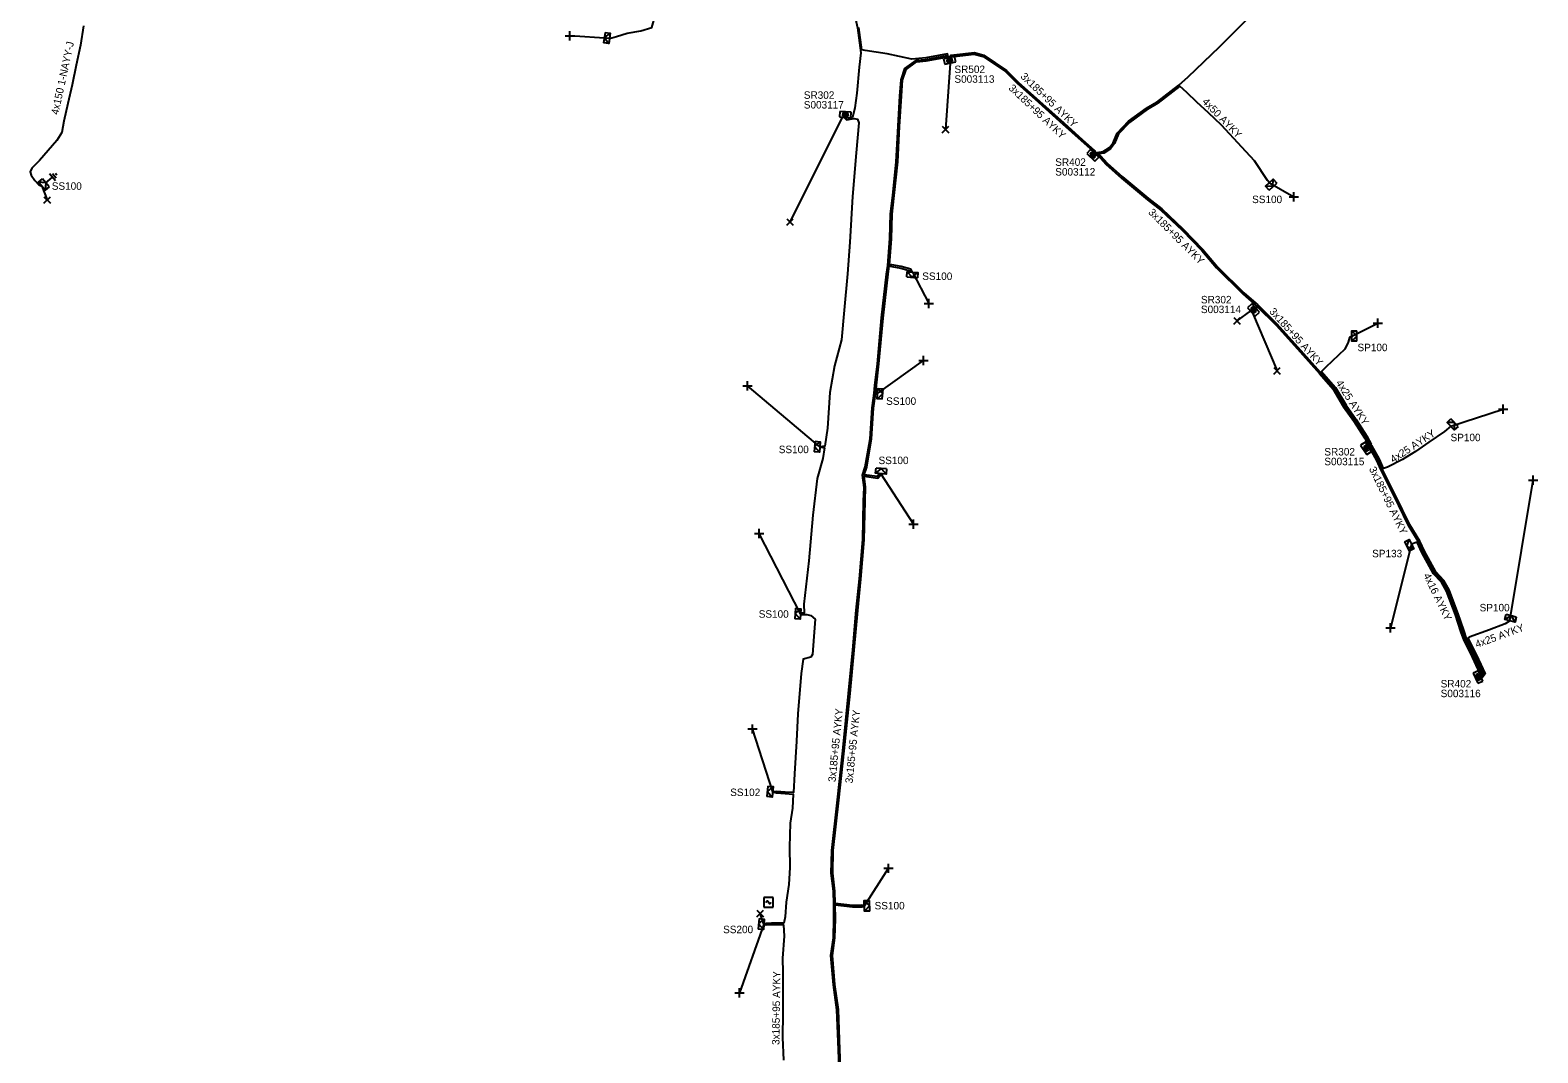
# Model space of a CAD drawing. Extents: x -763093 to -760976, y -1155572 to -1152009.
# Drawn here: x -762866.2 to -762664.6, y -1152405.9 to -1152269.2 of the extents above; entities that cross this region are included whole.
import ezdxf

# ---------------------------------------------------------------- set-up
doc = ezdxf.new("R2010")
doc.units = 0
for name, color, linetype in [('Vrstva 1', 7, 'Continuous'), ('Vrstva 14', 7, 'Continuous'), ('Vrstva 15', 7, 'Continuous'), ('Vrstva 28', 7, 'Continuous'), ('Vrstva 29', 7, 'Continuous'), ('Vrstva 30', 7, 'Continuous'), ('Vrstva 31', 7, 'Continuous'), ('Vrstva 33', 7, 'Continuous'), ('Vrstva 34', 7, 'Continuous'), ('Vrstva 5', 7, 'Continuous'), ('Vrstva 59', 7, 'Continuous'), ('Vrstva 6', 7, 'Continuous'), ('Vrstva 8', 7, 'Continuous'), ('Vrstva 9', 7, 'Continuous')]:
    doc.layers.add(name, color=color, linetype=linetype)

# ---------------------------------------------------------------- blocks, each defined once
blk = doc.blocks.new('NN800')
at = {"layer": 'Vrstva 1'}
for points in [[(-0.44, 0.44), (0.44, -0.44)], [(-0.44, -0.44), (0.44, 0.44)]]:
    blk.add_lwpolyline(points, dxfattribs=at)
blk = doc.blocks.new('NN620')
at = {"layer": 'Vrstva 8'}
for points in [[(0.75, 0), (-0.75, 0)], [(-0.75, 0), (-0.75, -0.75)], [(0.75, -0.75), (0.75, 0)], [(-0.75, -0.75), (0.75, -0.75)], [(0.37, -0.18), (-0.38, -0.18)], [(-0.38, -0.18), (-0.38, -0.56)], [(-0.38, -0.56), (0.37, -0.56)], [(0.32, -0.23), (-0.33, -0.23)], [(-0.33, -0.23), (-0.33, -0.51)], [(-0.33, -0.51), (0.32, -0.51)], [(0.27, -0.27), (-0.28, -0.27)], [(-0.28, -0.27), (-0.28, -0.46)], [(-0.28, -0.46), (0.27, -0.46)], [(0.23, -0.32), (-0.23, -0.32)], [(-0.23, -0.32), (-0.23, -0.42)], [(-0.23, -0.42), (0.23, -0.42)], [(-0.19, -0.37), (0.19, -0.37)], [(0.23, -0.42), (0.23, -0.32)], [(0.27, -0.46), (0.27, -0.27)], [(0.32, -0.51), (0.32, -0.23)], [(0.37, -0.56), (0.37, -0.18)]]:
    blk.add_lwpolyline(points, dxfattribs=at)
blk = doc.blocks.new('NN630')
at = {"layer": 'Vrstva 9'}
for points in [[(0, -0.7), (-0.7, 0)], [(-0.7, -0.7), (-0.7, 0), (0.7, 0), (0.7, -0.7)], [(-0.7, -0.7), (0.7, -0.7)], [(0, -0.7), (0.7, 0)]]:
    blk.add_lwpolyline(points, dxfattribs=at)
blk = doc.blocks.new('NN810')
at = {"layer": 'Vrstva 14'}
for points in [[(0.63, -1.89), (-0.62, -1.89)], [(0, -0.64), (0, -1.89)], [(0.39, -2.2), (-0.4, -2.2)], [(0, -2.52), (-0.12, -2.52)], [(0.14, -2.52), (0, -2.52)]]:
    blk.add_lwpolyline(points, dxfattribs=at)
blk = doc.blocks.new('NN740')
at = {"layer": 'Vrstva 1'}
for points in [[(0.62, 0.62), (-0.63, 0.62)], [(-0.63, 0.62), (-0.63, -0.63)], [(0, 0), (0, 0.01), (0, 0.03), (-0.01, 0.05), (-0.01, 0.06), (-0.02, 0.08), (-0.03, 0.09), (-0.04, 0.1), (-0.05, 0.11), (-0.06, 0.12), (-0.08, 0.13), (-0.09, 0.14), (-0.11, 0.14), (-0.12, 0.15), (-0.14, 0.15), (-0.15, 0.15), (-0.17, 0.15), (-0.18, 0.15), (-0.2, 0.15), (-0.21, 0.14), (-0.23, 0.13), (-0.24, 0.12), (-0.26, 0.11), (-0.27, 0.1), (-0.28, 0.09), (-0.29, 0.08), (-0.29, 0.06), (-0.3, 0.05), (-0.3, 0.03), (-0.31, 0.02), (-0.31, 0), (-0.31, 0)], [(0.62, -0.63), (0.62, 0.62)], [(-0.63, -0.63), (0.62, -0.63)], [(0, 0), (0, -0.02), (0, -0.03), (0.01, -0.05), (0.01, -0.06), (0.02, -0.08), (0.03, -0.09), (0.04, -0.1), (0.05, -0.11), (0.06, -0.12), (0.07, -0.13), (0.09, -0.14), (0.1, -0.15), (0.12, -0.15), (0.13, -0.15), (0.15, -0.15), (0.16, -0.15), (0.18, -0.15), (0.19, -0.15), (0.21, -0.14), (0.22, -0.14), (0.24, -0.13), (0.25, -0.12), (0.26, -0.11), (0.27, -0.09), (0.28, -0.08), (0.29, -0.07), (0.29, -0.05), (0.3, -0.04), (0.3, -0.02), (0.3, -0.01), (0.3, -0.01)]]:
    blk.add_lwpolyline(points, dxfattribs=at)

msp = doc.modelspace()

# ---------------------------------------------------------------- linework, layer by layer
at = {"layer": 'Vrstva 5'}
for points in [[(-762777.22, -1152244.01), (-762776.91, -1152243.04), (-762776.6, -1152242.48), (-762775.28, -1152243.88), (-762772.47, -1152245.98), (-762769.84, -1152248.34), (-762766.96, -1152250.61), (-762764.08, -1152252.76), (-762761.25, -1152255.63), (-762760.02, -1152256.98), (-762758.84, -1152259.01), (-762758.01, -1152260.5), (-762757.4, -1152261.86), (-762757.19, -1152263.08), (-762756.18, -1152265.93), (-762755.53, -1152268.93), (-762755.1, -1152272.27), (-762755.29, -1152274.2), (-762755.64, -1152277.65), (-762755.88, -1152279.62), (-762756.2, -1152280.89), (-762756.92, -1152280.98), (-762757.08, -1152280.85)], [(-762788.68, -1152270.34), (-762787.75, -1152270.1), (-762786.31, -1152269.64), (-762784.5, -1152269.34), (-762783.04, -1152268.9), (-762782.58, -1152267.32), (-762781.96, -1152263.9), (-762781.27, -1152262.03), (-762780.25, -1152259.57), (-762779.44, -1152256.84), (-762778.72, -1152252.78), (-762778.22, -1152249.01), (-762777.67, -1152246.04), (-762777.5, -1152245.02), (-762777.34, -1152245.06)], [(-762859.02, -1152268.65), (-762859.42, -1152271.23), (-762860, -1152273.9), (-762860.55, -1152276.53), (-762861.12, -1152279.05), (-762861.66, -1152281.42), (-762861.91, -1152282.92), (-762862.6, -1152283.97), (-762863.76, -1152285.3), (-762864.91, -1152286.67), (-762865.93, -1152287.69), (-762866.15, -1152288.16), (-762866, -1152288.62), (-762865.54, -1152289.35), (-762865.01, -1152289.93), (-762864.59, -1152290.1)], [(-762743.38, -1152272.93), (-762743.49, -1152272.42), (-762746.41, -1152272.94), (-762748.27, -1152273.12), (-762751.55, -1152272.38), (-762754.51, -1152271.97), (-762754.96, -1152271.85), (-762755.33, -1152268.89)], [(-762723.83, -1152285.69), (-762723.51, -1152285.6), (-762722.67, -1152285.47), (-762721.85, -1152284.92), (-762721.33, -1152284.3), (-762720.82, -1152283.01), (-762719.3, -1152281.41), (-762716.9, -1152279.66), (-762715.49, -1152278.85), (-762712.58, -1152276.58), (-762711.33, -1152275.47), (-762707.12, -1152271.46), (-762703.51, -1152267.85)], [(-762757.8, -1152413.28), (-762758.08, -1152405.45), (-762758.29, -1152400.15), (-762758.76, -1152396.81), (-762759.08, -1152392.88), (-762758.76, -1152390.54), (-762758.68, -1152387.98), (-762758.7, -1152386.03), (-762758.76, -1152384.31), (-762759.03, -1152381.88), (-762758.98, -1152378.85), (-762758.21, -1152372.1), (-762757.5, -1152365.54), (-762756.72, -1152357.88), (-762756.16, -1152352.07), (-762755.69, -1152346.77), (-762755.27, -1152342.58), (-762754.83, -1152337.31), (-762754.71, -1152332.19), (-762754.64, -1152330.34), (-762754.88, -1152328.72), (-762754.49, -1152327.58), (-762753.85, -1152323.84), (-762753.59, -1152319.72), (-762753.3, -1152317.75), (-762753.2, -1152316.68), (-762752.86, -1152313.81), (-762752.32, -1152307.69), (-762751.64, -1152301.83), (-762751.48, -1152300.67), (-762751.19, -1152297.09), (-762751.1, -1152293.79), (-762750.82, -1152291.3), (-762750.34, -1152286.82), (-762750.11, -1152282.08), (-762749.85, -1152278.02), (-762749.7, -1152275.89), (-762749.21, -1152274.36), (-762747.64, -1152273.26), (-762746.38, -1152273.14), (-762743.56, -1152272.64), (-762743.49, -1152272.95)], [(-762757.6, -1152413.28), (-762757.88, -1152405.45), (-762758.09, -1152400.13), (-762758.56, -1152396.79), (-762758.88, -1152392.88), (-762758.56, -1152390.56), (-762758.48, -1152387.98), (-762758.5, -1152386.14), (-762756.2, -1152386.4), (-762754.95, -1152386.38), (-762754.61, -1152386.27), (-762754.95, -1152386.18), (-762756.2, -1152386.2), (-762758.5, -1152385.94), (-762758.56, -1152384.29), (-762758.83, -1152381.88), (-762758.78, -1152378.87), (-762758.01, -1152372.12), (-762757.3, -1152365.56), (-762756.52, -1152357.9), (-762755.96, -1152352.09), (-762755.49, -1152346.79), (-762755.07, -1152342.6), (-762754.63, -1152337.33), (-762754.51, -1152332.19), (-762754.44, -1152330.32), (-762754.66, -1152328.85), (-762752.81, -1152329.1), (-762752.5, -1152328.76), (-762752.41, -1152328.51), (-762752.66, -1152328.63), (-762752.89, -1152328.88), (-762754.65, -1152328.65), (-762754.29, -1152327.62), (-762753.65, -1152323.86), (-762753.39, -1152319.74), (-762753.12, -1152317.87), (-762752.86, -1152317.81), (-762753.09, -1152317.67), (-762753, -1152316.7), (-762752.66, -1152313.83), (-762752.12, -1152307.71), (-762751.44, -1152301.85), (-762751.29, -1152300.79), (-762750.94, -1152300.82), (-762749.74, -1152301.04), (-762748.51, -1152301.38), (-762748.18, -1152301.57), (-762748.41, -1152301.2), (-762749.7, -1152300.84), (-762750.92, -1152300.62), (-762751.27, -1152300.59), (-762750.99, -1152297.11), (-762750.9, -1152293.81), (-762750.62, -1152291.32), (-762750.14, -1152286.84), (-762749.91, -1152282.1), (-762749.65, -1152278.04), (-762749.5, -1152275.93), (-762749.03, -1152274.48), (-762747.62, -1152273.46), (-762746.35, -1152273.34), (-762743.63, -1152272.86), (-762743.59, -1152273.03)], [(-762743.29, -1152272.91), (-762743.04, -1152272.59), (-762739.9, -1152272.23), (-762738.63, -1152272.56), (-762735.6, -1152274.61), (-762734.06, -1152276.17), (-762731.19, -1152278.74), (-762728.39, -1152281.24), (-762725.48, -1152283.83), (-762723.84, -1152285.3), (-762723.76, -1152285.59), (-762723.45, -1152285.6), (-762722.17, -1152287), (-762720.08, -1152288.84), (-762716.62, -1152291.75), (-762714.83, -1152293.13), (-762711.98, -1152295.84), (-762709.37, -1152298.56), (-762707.39, -1152300.86), (-762703.89, -1152304.34), (-762702.01, -1152305.95), (-762702.38, -1152306.31)], [(-762743.15, -1152272.88), (-762742.96, -1152272.79), (-762739.92, -1152272.43), (-762738.71, -1152272.74), (-762735.72, -1152274.77), (-762734.2, -1152276.31), (-762731.33, -1152278.88), (-762728.53, -1152281.38), (-762725.62, -1152283.97), (-762724.02, -1152285.42), (-762723.97, -1152285.56)], [(-762700.46, -1152289.63), (-762700.72, -1152289.33), (-762702.43, -1152286.72), (-762704.14, -1152284.86), (-762706.84, -1152281.95), (-762708.61, -1152280.27), (-762710.14, -1152278.88), (-762711.49, -1152277.58), (-762712.44, -1152276.73), (-762715.37, -1152279.01), (-762716.8, -1152279.82), (-762719.16, -1152281.57), (-762720.64, -1152283.11), (-762721.15, -1152284.4), (-762721.71, -1152285.08), (-762722.59, -1152285.67), (-762723.5, -1152285.8), (-762723.72, -1152285.79)], [(-762757.34, -1152280.88), (-762756.98, -1152281.2), (-762755.96, -1152281.05), (-762755.55, -1152281.15), (-762755.36, -1152281.6), (-762755.73, -1152285.65), (-762756.22, -1152291.48), (-762756.57, -1152297.56), (-762756.87, -1152301.81), (-762757.33, -1152306.65), (-762757.67, -1152310.61), (-762758.61, -1152314.09), (-762759.25, -1152317.67), (-762759.55, -1152322.43), (-762759.9, -1152324.85), (-762760.56, -1152324.93), (-762759.93, -1152325.05), (-762760.15, -1152326.47), (-762760.92, -1152329.17), (-762761.5, -1152334.06), (-762762.03, -1152340.14), (-762762.72, -1152345.93), (-762762.68, -1152347.14), (-762762.94, -1152347.15), (-762763.16, -1152347.25), (-762762.94, -1152347.35), (-762762.31, -1152347.33), (-762761.75, -1152347.47), (-762761.17, -1152347.97), (-762761.36, -1152350.28), (-762761.54, -1152352.66), (-762761.79, -1152353.03), (-762762.81, -1152353.28), (-762763.07, -1152355.21), (-762763.5, -1152360.61), (-762763.7, -1152364.24), (-762763.94, -1152368.62), (-762764.1, -1152371.12), (-762765.18, -1152371.05), (-762766.38, -1152370.97), (-762766.87, -1152371.03), (-762766.38, -1152371.17), (-762765.2, -1152371.25), (-762764.12, -1152371.32), (-762764.22, -1152373.21), (-762764.53, -1152375.22), (-762764.6, -1152378.43), (-762764.59, -1152381.16), (-762764.71, -1152383.43), (-762765.08, -1152385.77), (-762765.22, -1152387.72), (-762765.4, -1152388.58), (-762767.05, -1152388.56), (-762767.72, -1152388.61), (-762768.05, -1152388.73), (-762767.72, -1152388.81), (-762767.05, -1152388.76), (-762765.41, -1152388.78), (-762765.32, -1152390.32), (-762765.57, -1152393.24), (-762765.52, -1152395.18), (-762765.52, -1152400.62), (-762765.56, -1152403.85), (-762765.41, -1152406.87)], [(-762723.6, -1152285.9), (-762723.45, -1152285.9), (-762722.31, -1152287.14), (-762720.22, -1152289), (-762716.74, -1152291.91), (-762714.97, -1152293.29), (-762712.12, -1152295.98), (-762709.51, -1152298.7), (-762707.53, -1152301), (-762704.03, -1152304.48), (-762702.08, -1152306.16), (-762699.54, -1152308.68), (-762696.34, -1152312.24), (-762693.77, -1152315.11), (-762691.94, -1152317.23), (-762690.53, -1152319.57), (-762689.19, -1152321.48), (-762687.75, -1152323.7), (-762687.29, -1152324.6), (-762687.42, -1152324.69)], [(-762672.16, -1152355.64), (-762671.84, -1152355.22), (-762672.96, -1152352.86), (-762674.06, -1152350.65), (-762674.48, -1152349.44), (-762675.2, -1152347.23), (-762676.43, -1152344.05), (-762677.14, -1152342.77), (-762678.2, -1152341.64), (-762679.73, -1152338.87), (-762680.35, -1152337.52), (-762681.66, -1152335.33), (-762683.62, -1152331.32), (-762685.38, -1152327.85), (-762685.92, -1152326.65), (-762686.98, -1152324.76), (-762687.58, -1152323.6), (-762689.02, -1152321.37), (-762690.36, -1152319.46), (-762691.78, -1152317.11), (-762693.62, -1152314.98), (-762696.2, -1152312.1), (-762699.4, -1152308.54), (-762701.87, -1152306.09), (-762702.24, -1152306.45)], [(-762689.45, -1152310.11), (-762689.73, -1152310.32), (-762689.94, -1152310.95), (-762690.38, -1152311.87), (-762692.91, -1152314.27), (-762693.48, -1152314.84), (-762691.62, -1152316.99), (-762690.19, -1152319.35), (-762688.85, -1152321.26), (-762687.41, -1152323.5), (-762686.86, -1152324.56), (-762687.28, -1152324.84)], [(-762676.22, -1152322.16), (-762677.06, -1152322.86), (-762679.13, -1152324.29), (-762680.94, -1152325.56), (-762682.66, -1152326.6), (-762684.66, -1152327.66), (-762685.18, -1152327.8), (-762685.74, -1152326.56), (-762686.76, -1152324.74), (-762687.16, -1152325)], [(-762672.26, -1152355.44), (-762672.08, -1152355.2), (-762673.14, -1152352.94), (-762674.24, -1152350.73), (-762674.67, -1152349.51), (-762675.39, -1152347.3), (-762676.61, -1152344.13), (-762677.3, -1152342.89), (-762678.36, -1152341.76), (-762679.91, -1152338.96), (-762680.53, -1152337.6), (-762681.84, -1152335.43), (-762683.8, -1152331.4), (-762685.56, -1152327.93), (-762686.1, -1152326.74), (-762687, -1152325.13)], [(-762672.31, -1152355.17), (-762673.32, -1152353.03), (-762674.42, -1152350.82), (-762674.86, -1152349.58), (-762675.58, -1152347.37), (-762676.79, -1152344.21), (-762677.46, -1152343.01), (-762678.52, -1152341.88), (-762680.09, -1152339.05), (-762680.72, -1152337.67), (-762681.45, -1152337.94)], [(-762668.29, -1152348.18), (-762668.92, -1152348.58), (-762671.01, -1152349.37), (-762673.75, -1152350.37), (-762673.91, -1152350.5), (-762672.78, -1152352.77), (-762671.61, -1152355.25), (-762672.07, -1152355.85)]]:
    msp.add_lwpolyline(points, dxfattribs=at)
at = {"layer": 'Vrstva 59'}
for points in [[(-762788.68, -1152270.34), (-762794, -1152270)], [(-762743.15, -1152273.63), (-762743.75, -1152282.5)], [(-762757.57, -1152280.88), (-762764.56, -1152294.88)], [(-762700.46, -1152289.63), (-762697.19, -1152291.5)], [(-762864.59, -1152290.1), (-762863.89, -1152291.93)], [(-762748.18, -1152301.57), (-762746, -1152305.75)], [(-762702.98, -1152306.76), (-762704.79, -1152308.08)], [(-762702.73, -1152307.03), (-762699.44, -1152314.75)], [(-762689.45, -1152310.11), (-762685.94, -1152308.38)], [(-762752.86, -1152317.81), (-762746.69, -1152313.38)], [(-762760.56, -1152324.93), (-762770.25, -1152316.75)], [(-762676.22, -1152322.16), (-762669.19, -1152319.88)], [(-762752.41, -1152328.51), (-762748.06, -1152335.25)], [(-762668.29, -1152348.18), (-762665.19, -1152329.38)], [(-762763.16, -1152347.25), (-762768.69, -1152336.5)], [(-762681.45, -1152337.94), (-762684.25, -1152349.13)], [(-762766.87, -1152371.03), (-762769.56, -1152362.63)], [(-762754.61, -1152386.27), (-762751.38, -1152381.25)], [(-762768.05, -1152388.73), (-762768.56, -1152387.3)], [(-762768.05, -1152388.73), (-762771.31, -1152397.88)]]:
    msp.add_lwpolyline(points, dxfattribs=at)

# ---------------------------------------------------------------- block references
at = {"layer": 'Vrstva 15', "rotation": 130.60141040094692}
msp.add_blockref('NN810', (-762864.59, -1152290.1), dxfattribs=at)
at = {"layer": 'Vrstva 28'}
for p, rotation in [((-762743.29, -1152272.91), 11.863461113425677), ((-762757.18, -1152280.89), 176.12682012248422), ((-762723.83, -1152285.69), -42.35830100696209), ((-762702.31, -1152306.38), -47.00935499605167), ((-762687.22, -1152324.92), -57.46023708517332), ((-762672.21, -1152355.54), -66.73196604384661)]:
    msp.add_blockref('NN620', p, dxfattribs=dict(at, rotation=rotation))
at = {"layer": 'Vrstva 31'}
for p, rotation in [((-762788.68, -1152270.34), -98.00232040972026), ((-762864.59, -1152290.1), 130.60141040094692), ((-762700.46, -1152289.63), 42.45662503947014), ((-762748.18, -1152301.57), -3.9728303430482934), ((-762689.45, -1152310.11), 90), ((-762752.86, -1152317.81), 85.87478051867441), ((-762676.22, -1152322.16), 133.1402192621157), ((-762760.56, -1152324.93), -94.76171392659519), ((-762752.41, -1152328.51), 175.67250838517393), ((-762681.45, -1152337.94), -64.63601383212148), ((-762763.16, -1152347.25), -94.42481608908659), ((-762668.29, -1152348.18), 166.4073739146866), ((-762766.87, -1152371.03), -95.57836302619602), ((-762754.61, -1152386.27), 91.21513338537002), ((-762768.05, -1152388.73), -95.00694085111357)]:
    msp.add_blockref('NN630', p, dxfattribs=dict(at, rotation=rotation))
at = {"layer": 'Vrstva 34'}
for p, rotation in [((-762794, -1152270), 45), ((-762697.19, -1152291.5), 44.99999995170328), ((-762746, -1152305.75), 45), ((-762685.94, -1152308.38), 44.99999995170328), ((-762746.69, -1152313.38), 44.99999995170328), ((-762770.25, -1152316.75), 45), ((-762669.19, -1152319.88), 44.99999995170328), ((-762665.19, -1152329.38), 44.99999995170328), ((-762768.69, -1152336.5), 44.99999995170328), ((-762748.06, -1152335.25), 45), ((-762684.25, -1152349.13), 45), ((-762769.56, -1152362.63), 45), ((-762751.38, -1152381.25), 45), ((-762771.31, -1152397.88), 45)]:
    msp.add_blockref('NN800', p, dxfattribs=dict(at, rotation=rotation))
for name, p in [('NN800', (-762743.75, -1152282.5)), ('NN800', (-762863.89, -1152291.93)), ('NN800', (-762764.56, -1152294.88)), ('NN800', (-762704.79, -1152308.08)), ('NN800', (-762699.44, -1152314.75)), ('NN740', (-762767.43, -1152385.79)), ('NN800', (-762768.56, -1152387.3))]:
    msp.add_blockref(name, p, dxfattribs=at)

# ---------------------------------------------------------------- texts
at = {"layer": 'Vrstva 29'}
for s, p in [('S003113', (-762742.57, -1152276.27)), ('S003117', (-762762.71, -1152279.71)), ('S003112', (-762729.09, -1152288.67)), ('S003114', (-762709.61, -1152307.05)), ('S003115', (-762693.11, -1152327.38)), ('S003116', (-762677.56, -1152358.38))]:
    msp.add_text(s, height=1, dxfattribs=at).set_placement(p)
at = {"layer": 'Vrstva 30'}
for s, p in [('SR502', (-762742.57, -1152274.97)), ('SR302', (-762762.71, -1152278.41)), ('SR402', (-762729.09, -1152287.37)), ('SR302', (-762709.61, -1152305.75)), ('SR302', (-762693.11, -1152326.08)), ('SR402', (-762677.56, -1152357.08))]:
    msp.add_text(s, height=1, dxfattribs=at).set_placement(p)
at = {"layer": 'Vrstva 33'}
for s, p in [('SS100', (-762863.26, -1152290.57)), ('SS100', (-762702.77, -1152292.35)), ('SS100', (-762746.87, -1152302.62)), ('SP100', (-762688.68, -1152312.14)), ('SS100', (-762751.7, -1152319.31)), ('SP100', (-762676.24, -1152324.17)), ('SS100', (-762766.06, -1152325.77)), ('SS100', (-762752.72, -1152327.23)), ('SP133', (-762686.72, -1152339.68)), ('SP100', (-762672.35, -1152346.91)), ('SS100', (-762768.74, -1152347.76)), ('SS102', (-762772.55, -1152371.59)), ('SS100', (-762753.24, -1152386.74)), ('SS200', (-762773.5, -1152389.92))]:
    msp.add_text(s, height=1, dxfattribs=at).set_placement(p)
at = {"layer": 'Vrstva 6'}
for s, rotation, p in [('4x150 1-NAYY-J', 77.744, (-762862.39, -1152280.61)), ('3x185+95 AYKY', 316.243, (-762733.81, -1152275.52)), ('3x185+95 AYKY', 316.587, (-762735.41, -1152277.08)), ('4x50 AYKY', 314.296, (-762709.52, -1152278.88)), ('3x185+95 AYKY', 315, (-762716.73, -1152293.66)), ('3x185+95 AYKY', 312.062, (-762700.54, -1152306.89)), ('4x25 AYKY', 302.775, (-762691.62, -1152316.38)), ('4x25 AYKY', 33.214, (-762683.89, -1152327.12)), ('3x185+95 AYKY', 295.894, (-762687.17, -1152327.86)), ('4x16 AYKY', 295.67, (-762679.9, -1152342.09)), ('4x25 AYKY', 20.072, (-762672.73, -1152351.81)), ('3x185+95 AYKY', 84.229, (-762758.47, -1152369.76)), ('3x185+95 AYKY', 84.094, (-762756.19, -1152369.93)), ('3x185+95 AYKY', 89.178, (-762765.97, -1152404.86))]:
    msp.add_text(s, height=1, rotation=rotation, dxfattribs=at).set_placement(p)

doc.saveas('drawing.dxf')
